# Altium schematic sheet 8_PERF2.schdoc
size 302 x 215 mm; Symbol: Sheet_A4; Device: Sheet_A4; @Project Name: Avaota A1 八核 AIoT 开发板; @Page No: 9; @Page Count: 13; @Update Date: 2024-04-03
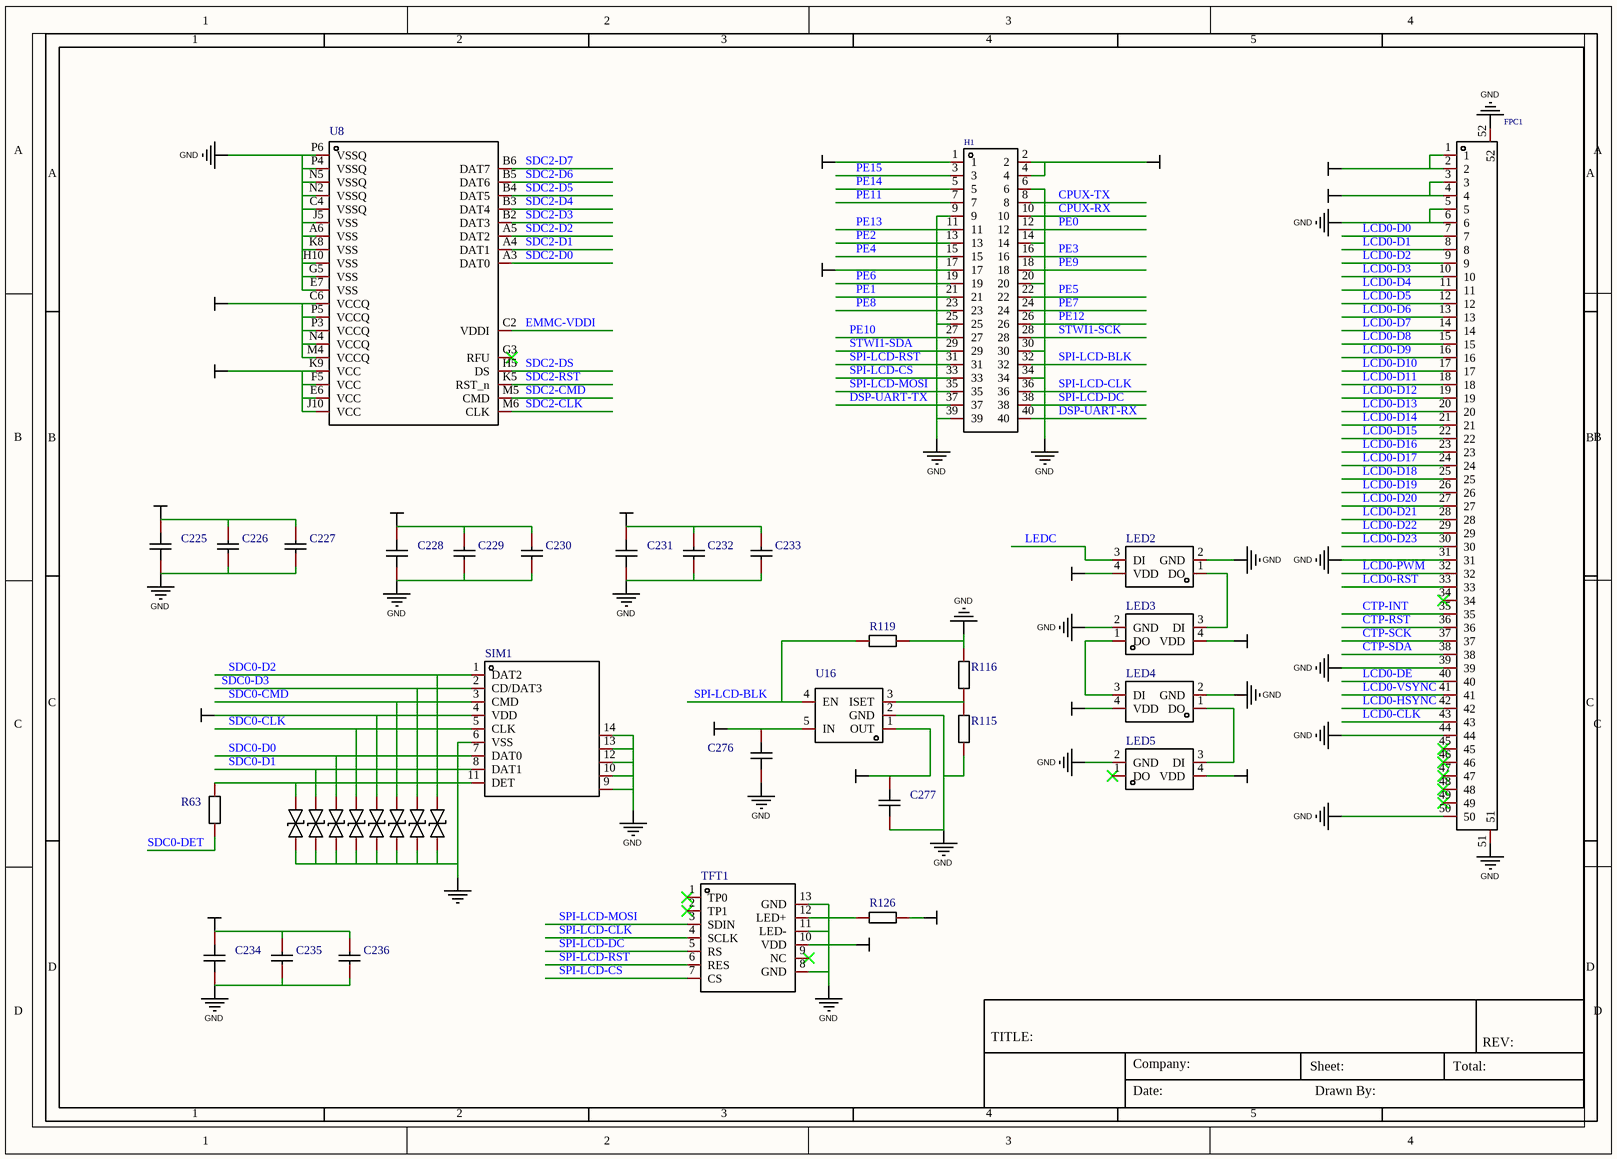
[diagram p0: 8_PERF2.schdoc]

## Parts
C225  0201X225M6R3NT  [c0201 nsk]  (value not drawn)
C226  GRM033R61A104KE15D  [c0201 nsk]  (value not drawn)
C227  GRM033R61A104KE15D  [c0201 nsk]  (value not drawn)
C228  0201X225M6R3NT  [c0201 nsk]  (value not drawn)
C229  GRM033R61A104KE15D  [c0201 nsk]  (value not drawn)
C230  GRM033R61A104KE15D  [c0201 nsk]  (value not drawn)
C231  0201X225M6R3NT  [c0201 nsk]  (value not drawn)
C232  GRM033R61A104KE15D  [c0201 nsk]  (value not drawn)
C233  GRM033R61A104KE15D  [c0201 nsk]  (value not drawn)
C234  0201X225M6R3NT  [c0201 nsk]  (value not drawn)
C235  GRM033R61A104KE15D  [c0201 nsk]  (value not drawn)
C236  GRM033R61A104KE15D  [c0201 nsk]  (value not drawn)
C276  0201X225M6R3NT  [c0201 nsk]  (value not drawn)
C277  0201X225M6R3NT  [c0201 nsk]  (value not drawn)
D16  0402ESDA-05N  [D0402]  (value not drawn)
D17  0402ESDA-05N  [D0402]  (value not drawn)
D18  0402ESDA-05N  [D0402]  (value not drawn)
D19  0402ESDA-05N  [D0402]  (value not drawn)
D20  0402ESDA-05N  [D0402]  (value not drawn)
D21  0402ESDA-05N  [D0402]  (value not drawn)
D22  0402ESDA-05N  [D0402]  (value not drawn)
D23  0402ESDA-05N  [D0402]  (value not drawn)
FPC1  FPC-05FB-50PH20  [FPC-SMD_50P-P0.50_FPC-05FB-50PH20]  (value not drawn)
H1  12251220ANG0S115001  [HDR-TH_40P-P2.54-V-M-R2-C20-S2.54]  (value not drawn)
LED2  WS2812B-2020  [LED-SMD_4P-L2.0-W2.0-TL_WS2812B-2020]  (value not drawn)
LED3  WS2812B-2020  [LED-SMD_4P-L2.0-W2.0-TL_WS2812B-2020]  (value not drawn)
LED4  WS2812B-2020  [LED-SMD_4P-L2.0-W2.0-TL_WS2812B-2020]  (value not drawn)
LED5  WS2812B-2020  [LED-SMD_4P-L2.0-W2.0-TL_WS2812B-2020]  (value not drawn)
R63  Res_0201  [r0201 nsk]  (value not drawn)
R115  Res_0201  [r0201 nsk]  (value not drawn)
R116  Res_0201  [r0201 nsk]  (value not drawn)
R119  Res_0201  [r0201 nsk]  (value not drawn)
R126  Res_0402  [R0402-NSK]  (value not drawn)
SIM1  1040310811  [SIM-SMD_8P-1040310811]  (value not drawn)
TFT1  1.14 IPS DISPLAY ST7789V  [TFT_1.14寸_0.7MM-13P]  (value not drawn)
U8  EMMC BGA153  [FBGA-153_L13.0-W11.5]  (value not drawn)
U16  SY6280AAC_C55136  [SOT-23-5_L3.0-W1.7-P0.95-LS2.8-BL]  (value not drawn)

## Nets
EMMC-VDDI: C231.1 C232.2 C233.2 U8.C2(VDDI)
GND: C225.2 C226.1 C227.1 C228.2 C229.1 C230.1 C231.2 C232.1 C233.1 C234.2 C235.1 C236.1 C276.2 C277.1 D16.2 D17.1 D18.2 D19.1 D20.2 D21.1 D22.2 D23.1 FPC1.5 FPC1.6 FPC1.31 FPC1.39 FPC1.44 FPC1.50 FPC1.51 FPC1.52 H1.6 H1.9 H1.14 H1.20 H1.25 H1.30 H1.34 H1.39 LED2.2(GND) LED3.2(GND) LED4.2(GND) LED5.2(GND) R115.1 R116.2 R119.1 SIM1.6(VSS) SIM1.9 SIM1.10 SIM1.12 SIM1.13 SIM1.14 TFT1.8(GND) TFT1.11(LED-) TFT1.13(GND) U8.A6(VSS) U8.C4(VSSQ) U8.E7(VSS) U8.G5(VSS) U8.H10(VSS) U8.J5(VSS) U8.K8(VSS) U8.N2(VSSQ) U8.N5(VSSQ) U8.P4(VSSQ) U8.P6(VSSQ) U16.2(GND)
VBUS: FPC1.1 FPC1.2 H1.2 H1.4 LED2.4(VDD) LED3.4(VDD) LED4.4(VDD) LED5.4(VDD)
VCC-3V3: C276.1 FPC1.3 FPC1.4 H1.1 H1.17 TFT1.10(VDD) U16.5(IN)
VCC-3V3-BLK: C277.2 R126.2 U16.1(OUT)
VCC-CARD: C234.1 C235.2 C236.2 D20.1 SIM1.4(VDD)
VCC-NAND: C228.1 C229.2 C230.2 U8.E6(VCC) U8.F5(VCC) U8.J10(VCC) U8.K9(VCC)
VCC-PC: C225.1 C226.2 C227.2 U8.C6(VCCQ) U8.M4(VCCQ) U8.N4(VCCQ) U8.P3(VCCQ) U8.P5(VCCQ)
CPUX-RX: H1.10
CPUX-TX: H1.8
CTP-INT: FPC1.35
CTP-RST: FPC1.36
CTP-SCK: FPC1.37
CTP-SDA: FPC1.38
DSP-UART-RX: H1.40
DSP-UART-TX: H1.37
LCD0-CLK: FPC1.43
LCD0-D0: FPC1.7
LCD0-D1: FPC1.8
LCD0-D2: FPC1.9
LCD0-D3: FPC1.10
LCD0-D4: FPC1.11
LCD0-D5: FPC1.12
LCD0-D6: FPC1.13
LCD0-D7: FPC1.14
LCD0-D8: FPC1.15
LCD0-D9: FPC1.16
LCD0-D10: FPC1.17
LCD0-D11: FPC1.18
LCD0-D12: FPC1.19
LCD0-D13: FPC1.20
LCD0-D14: FPC1.21
LCD0-D15: FPC1.22
LCD0-D16: FPC1.23
LCD0-D17: FPC1.24
LCD0-D18: FPC1.25
LCD0-D19: FPC1.26
LCD0-D20: FPC1.27
LCD0-D21: FPC1.28
LCD0-D22: FPC1.29
LCD0-D23: FPC1.30
LCD0-DE: FPC1.40
LCD0-HSYNC: FPC1.42
LCD0-PWM: FPC1.32
LCD0-RST: FPC1.33
LCD0-VSYNC: FPC1.41
LEDC: LED2.3(DI)
PE0: H1.12
PE1: H1.21
PE2: H1.13
PE3: H1.16
PE4: H1.15
PE5: H1.22
PE6: H1.19
PE7: H1.24
PE8: H1.23
PE9: H1.18
PE10: H1.27
PE11: H1.7
PE12: H1.26
PE13: H1.11
PE14: H1.5
PE15: H1.3
SDC0-CLK: D19.2 SIM1.5(CLK)
SDC0-CMD: D21.2 SIM1.3(CMD)
SDC0-D0: D18.1 SIM1.7(DAT0)
SDC0-D1: D17.2 SIM1.8(DAT1)
SDC0-D2: D23.2 SIM1.1(DAT2)
SDC0-D3: D22.1 SIM1.2(CD/DAT3)
SDC0-DET: R63.1
SDC2-CLK: U8.M6(CLK)
SDC2-CMD: U8.M5(CMD)
SDC2-D0: U8.A3(DAT0)
SDC2-D1: U8.A4(DAT1)
SDC2-D2: U8.A5(DAT2)
SDC2-D3: U8.B2(DAT3)
SDC2-D4: U8.B3(DAT4)
SDC2-D5: U8.B4(DAT5)
SDC2-D6: U8.B5(DAT6)
SDC2-D7: U8.B6(DAT7)
SDC2-DS: U8.H5(DS)
SDC2-RST: U8.K5(RST_n)
SPI-LCD-BLK: H1.32 R119.2 U16.4(EN)
SPI-LCD-CLK: H1.36 TFT1.4(SCLK)
SPI-LCD-CS: H1.33 TFT1.7(CS)
SPI-LCD-DC: H1.38 TFT1.5(RS)
SPI-LCD-MOSI: H1.35 TFT1.3(SDIN)
SPI-LCD-RST: H1.31 TFT1.6(RES)
STWI1-SCK: H1.28
STWI1-SDA: H1.29
NetD16_1: D16.1 R63.2 SIM1.11(DET)
NetLED2_1: LED2.1(DO) LED3.3(DI)
NetLED3_1: LED3.1(DO) LED4.3(DI)
NetLED4_1: LED4.1(DO) LED5.3(DI)
NetR115_2: R115.2 R116.1 U16.3(ISET)
NetR126_1: R126.1 TFT1.12(LED+)

Not connected (* = marked no-connect by the designer): FPC1 34* 45* 46* 47* 48* 49*; LED5 1(DO)*; TFT1 1(TP0)* 2(TP1)* 9(NC)*; U8 G3(RFU)*

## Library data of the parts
C225 C228 C231 C234 C276 C277 = 0201X225M6R3NT: Manufacturer: FH(风华); Add into BOM: yes; Value: 2.2uF; Tolerance: ±20%; Voltage Rated: 6.3V; Temperature Coefficient: X5R; Description: 容值:2.2uF;精度:±20%;额定电压:6.3V;材质(温度系数):X5R;
C226 C227 C229 C230 C232 C233 C235 C236 = GRM033R61A104KE15D: Manufacturer: muRata(村田); Value: 100nF; Add into BOM: yes; Tolerance: ±10%; Voltage Rated: 10V; Temperature Coefficient: X5R; Description: 容值:100nF;精度:±10%;额定电压:10V;材质(温度系数):X5R;
D16-D23 = 0402ESDA-05N: Manufacturer: BORN(伯恩半导体); Add into BOM: yes; polarity: 双向; Reverse Stand-Off Voltage (Vrwm): 5V; Maximum Clamping Voltage: 50V; Type: ESD; Description: 极性:双向;反向截止电压(Vrwm):5V;钳位电压(Vc)@Ipp:50V;
FPC1 = FPC-05FB-50PH20: Manufacturer: XUNPU(讯普); Add into BOM: yes
H1 = 12251220ANG0S115001: Manufacturer: JILN(锦凌); Add into BOM: yes; Pin Structure: 2x20P; Pitch: 2.54mm; Circluar Pins/Square Pins: 方针; Current Rating (Max): 3A; Description: 插针结构:2x20P;间距:2.54mm;行距:2.54mm;圆针/方针:方针;安装类型:直插;排数:双排;总PIN位数:40P;额定电流:3A;额定电压:-;配合针长度:6mm;塑高:2.5mm;端接针长度:3mm;触头材质:黄铜;触头镀层:-;工作温度范围:-40℃~+105℃;颜色:黑色;
LED2-LED5 = WS2812B-2020: Manufacturer: worldsemi; Add into BOM: yes; Emitted Color: RGB三色; Dominant Wavelength: 470.4nm；622.5nm；515.6nm; Forward Current: 12mA; Description: 发光颜色:RGB三色;二极管配置:-;透镜颜色:-;主波长:470.4nm；622.5nm；515.6nm;峰值波长:-;色温:-;测试电流:12mA;功率:-;发光角度:-;安装方式:-;工作温度:-;
R63 = Res_0201: Symbol: 电阻; Convert to PCB: yes; Value: 10K
R115 R116 = Res_0201: Symbol: 电阻; Convert to PCB: yes; Value: 6K8
R119 = Res_0201: Symbol: 电阻; Convert to PCB: yes; Value: 100K
R126 = Res_0402: Symbol: 电阻; Convert to PCB: yes; Value: 10
SIM1 = 1040310811: Manufacturer: MOLEX; Add into BOM: yes; Card Connection Mode: 拔插式; Card Type: MicroSD卡(TF卡); Connector Type: 卡座; Maximum Body Height: 1.42mm; Description: 卡连接方式:拔插式;卡类型:MicroSD卡(TF卡);连接器类型:卡座;本体最大高度:1.42mm;触头镀层:金;工作温度范围:-;
TFT1 = 1.14 IPS DISPLAY ST7789V: Pin Type: IN; Add into BOM: yes
U8 = EMMC BGA153: Manufacturer: Kingston(金士顿); Manufacturer Part: EMMC04G-M627-A01; Pin Type: IN; Add into BOM: yes
U16 = SY6280AAC_C55136: Manufacturer: silergy(矽力杰); Add into BOM: yes; Description: 低能耗配电开关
